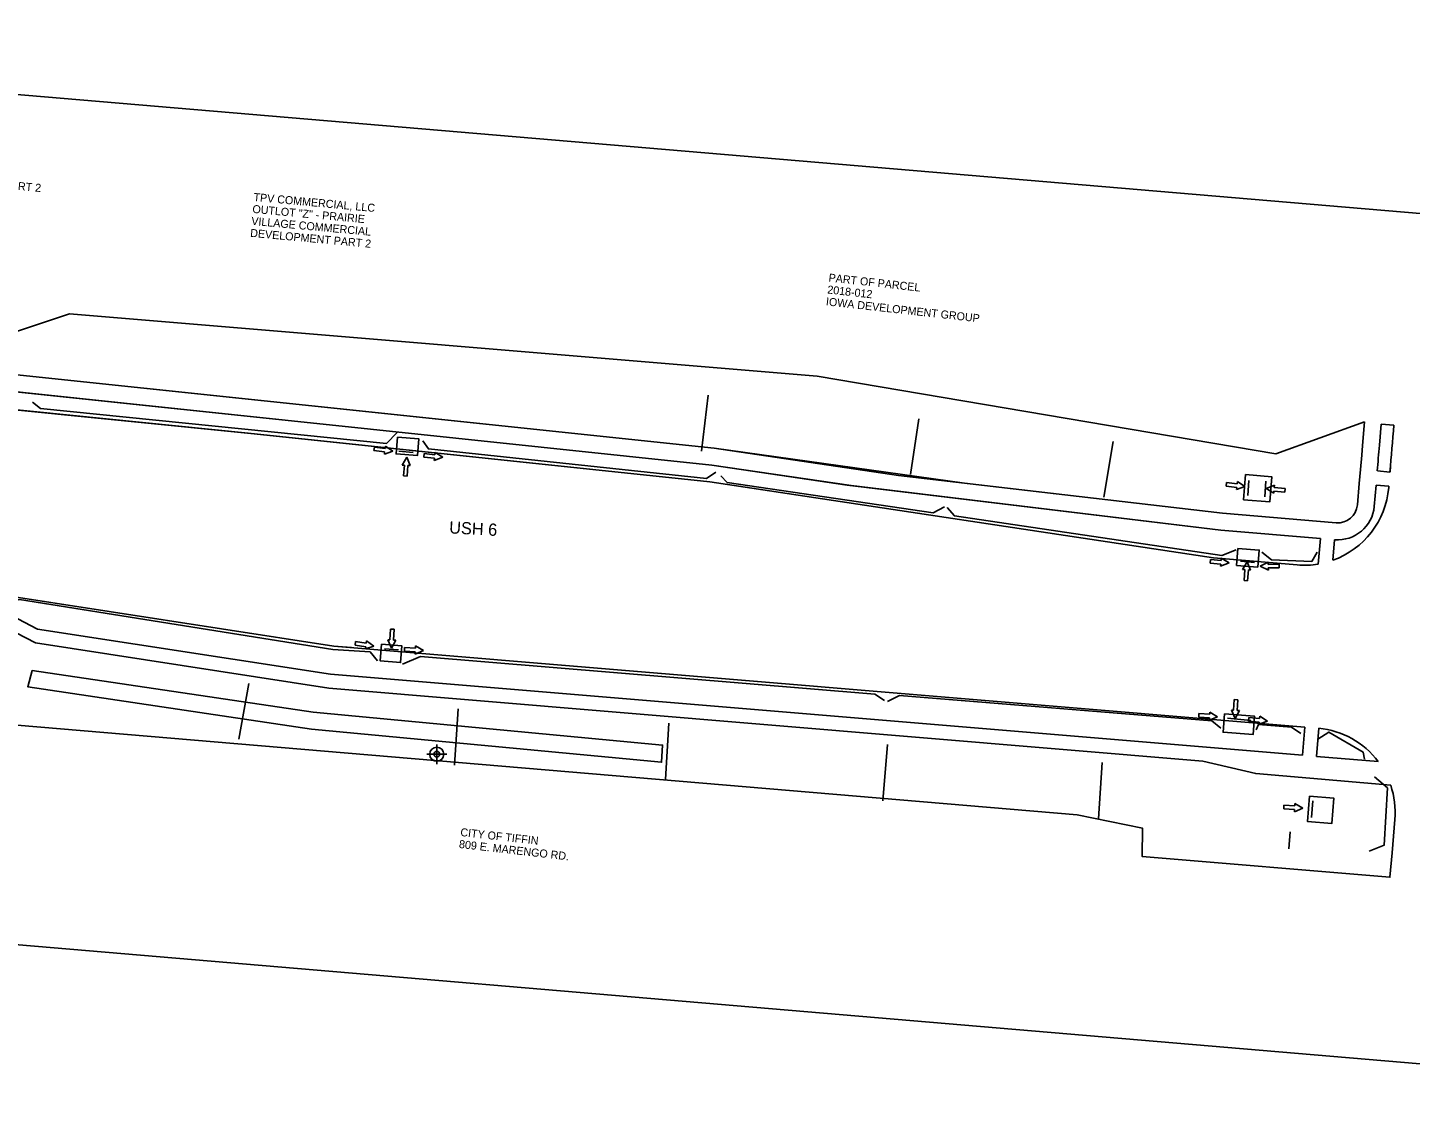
# Model space of a CAD drawing. Extents: x 20499990 to 20505779, y 7953198 to 7954399.
# Drawn here: x 20502718.2 to 20503207.9, y 7953607.1 to 7953985.5 of the extents above; entities that cross this region are included whole.
import ezdxf

# ---------------------------------------------------------------- set-up
doc = ezdxf.new("R2010")
doc.units = 0
for name, color, linetype in [('Building', 7, 'Continuous'), ('ClearGrub', 7, 'Continuous'), ('Curb', 7, 'Continuous'), ('dsnCellElements', 7, 'Continuous'), ('ErosionControl', 7, 'Continuous'), ('NamedBoundary', 7, 'Continuous'), ('Seeding', 7, 'Continuous'), ('Sidewalk', 7, 'Continuous'), ('Text', 7, 'Continuous')]:
    doc.layers.add(name, color=color, linetype=linetype)

msp = doc.modelspace()

# ---------------------------------------------------------------- linework, layer by layer
at = {"layer": 'Building'}
for p, q in [((20503190.96, 7953837.52), (20503191.67, 7953845.98)), ((20503196.96, 7953837.66), (20503197.62, 7953845.17)), ((20503197.63, 7953845.19), (20503202.11, 7953844.82)), ((20503190.68, 7953834.16), (20503190.96, 7953837.52)), ((20503190.26, 7953829.05), (20503190.68, 7953834.16)), ((20503189.82, 7953824.07), (20503190.26, 7953829.05)), ((20503200.7, 7953828.17), (20503196.22, 7953828.55)), ((20503138.13, 7953797.77), (20502959.75, 7953824.69)), ((20503189.15, 7953816.56), (20503189.82, 7953824.07)), ((20503195.13, 7953816.03), (20503195.79, 7953823.54)), ((20503195.8, 7953823.57), (20503200.28, 7953823.19)), ((20503176.04, 7953804.65), (20503175.29, 7953795.59)), ((20503180.43, 7953796.93), (20503181.04, 7953804.23)), ((20503167.85, 7953795.29), (20503138.13, 7953797.77)), ((20502826.66, 7953766.57), (20502648.32, 7953794.05)), ((20502824.89, 7953751.67), (20502720.94, 7953767.64)), ((20503170.48, 7953737.88), (20502826.66, 7953766.57)), ((20502825.48, 7953756.63), (20503169.65, 7953727.91)), ((20503169.65, 7953727.91), (20503170.48, 7953737.88)), ((20503175.47, 7953737.46), (20503174.64, 7953727.5)), ((20503174.64, 7953727.5), (20503196.49, 7953725.67)), ((20503201.45, 7953693.28), (20503202.44, 7953705.11))]:
    msp.add_line(p, q, dxfattribs=at)
for points in [[(20503191.67, 7953845.98), (20503160.23, 7953834.67), (20502997.8, 7953862.16), (20502732.96, 7953884.23), (20502696.7, 7953872.21), (20502598.22, 7953880.54), (20502597.36, 7953880.88)], [(20502596.77, 7953874.12), (20502646.43, 7953869.48), (20502697.39, 7953864.38), (20502801.98, 7953853.37), (20502961.27, 7953836.6), (20503050, 7953824.21), (20503141.39, 7953813.56), (20503181.6, 7953810.21)], [(20502600.82, 7953862.58), (20502601.24, 7953867.37), (20502650.63, 7953863.01), (20502697.4, 7953858.35), (20502809.34, 7953846.56), (20502960.51, 7953830.65), (20503008.42, 7953823.59), (20503140.79, 7953807.58), (20503176.04, 7953804.65)], [(20502959.75, 7953824.69), (20502796.27, 7953841.89), (20502607.78, 7953860.95)], [(20502720.94, 7953767.64), (20502706.88, 7953774.87), (20502647.4, 7953784.09), (20502613.61, 7953787.03), (20502598.23, 7953783.35), (20502571.26, 7953785.7)], [(20502648, 7953789.06), (20502707.64, 7953779.82), (20502721.7, 7953772.58), (20502825.48, 7953756.63)], [(20502567.99, 7953764), (20502613.1, 7953758.85), (20502612.25, 7953748.82), (20502698.25, 7953741.67), (20502701.89, 7953740.37), (20502705.93, 7953739.22), (20503089.85, 7953706.77), (20503113.09, 7953702.02), (20503112.96, 7953691.99), (20503200.66, 7953684.68), (20503201.45, 7953693.28)], [(20503200.94, 7953717.27), (20503153.17, 7953721.39), (20503134.36, 7953725.84), (20502824.89, 7953751.67)]]:
    msp.add_lwpolyline(points, dxfattribs=at)
for centre, radius, start, end in [((20522727.64, 7952187.52), 19595.74, 175.148457, 175.197296), ((20503853.76, 7953779.5), 659.38, 174.93948, 175.73374), ((20503170.34, 7953825.18), 30, 289.6452, 355.1856), ((20503182.18, 7953817.18), 7, 265.2365, 354.9395), ((20503182.18, 7953817.18), 13, 265.2365, 354.9395), ((20503170.34, 7953825.18), 30, 265.2301, 279.4946), ((20503172.54, 7953707.6), 30, 37.0399, 84.393), ((20503172.54, 7953707.6), 30, 355.2385, 18.8077)]:
    msp.add_arc(centre, radius, start, end, dxfattribs=at)
at = {"layer": 'ClearGrub'}
for p, q in [((20502859.58, 7953728.24), (20502866.58, 7953728.24)), ((20502863.08, 7953731.74), (20502863.08, 7953724.74))]:
    msp.add_line(p, q, dxfattribs=at)
for radius in [2.5, 1]:
    msp.add_circle((20502863.08, 7953728.24), radius, dxfattribs=at)
at = {"layer": 'Curb'}
msp.add_line((20503200.24, 7953822.66), (20503200.28, 7953823.19), dxfattribs=at)
at = {"layer": 'dsnCellElements'}
for p, q in [((20502840.82, 7953835.75), (20502840.98, 7953837.01)), ((20502844.61, 7953835.28), (20502840.82, 7953835.75)), ((20502840.98, 7953837.01), (20502844.76, 7953836.54)), ((20502844.76, 7953836.54), (20502844.86, 7953837.33)), ((20502844.86, 7953837.33), (20502847.52, 7953835.55)), ((20502847.52, 7953835.55), (20502844.51, 7953834.49)), ((20502844.51, 7953834.49), (20502844.61, 7953835.28)), ((20502850.8, 7953830.66), (20502852.44, 7953833.41)), ((20502852.44, 7953833.41), (20502853.65, 7953830.45)), ((20502858.47, 7953833.44), (20502858.59, 7953834.71)), ((20502862.27, 7953833.07), (20502858.47, 7953833.44)), ((20502858.59, 7953834.71), (20502862.39, 7953834.33)), ((20502865.18, 7953833.42), (20502862.19, 7953832.27)), ((20502862.19, 7953832.27), (20502862.27, 7953833.07)), ((20502862.39, 7953834.33), (20502862.47, 7953835.12)), ((20502862.47, 7953835.12), (20502865.18, 7953833.42)), ((20502851.59, 7953830.6), (20502850.8, 7953830.66)), ((20502851.31, 7953826.8), (20502851.59, 7953830.6)), ((20502852.57, 7953826.7), (20502851.31, 7953826.8)), ((20502852.86, 7953830.51), (20502852.57, 7953826.7)), ((20502853.65, 7953830.45), (20502852.86, 7953830.51)), ((20503142.64, 7953823.19), (20503142.79, 7953824.45)), ((20503146.42, 7953822.73), (20503142.64, 7953823.19)), ((20503142.79, 7953824.45), (20503146.58, 7953824)), ((20503149.34, 7953823.02), (20503146.33, 7953821.94)), ((20503146.33, 7953821.94), (20503146.42, 7953822.73)), ((20503146.58, 7953824), (20503146.67, 7953824.79)), ((20503146.67, 7953824.79), (20503149.34, 7953823.02)), ((20503156.8, 7953822.33), (20503159.79, 7953823.49)), ((20503159.52, 7953820.64), (20503156.8, 7953822.33)), ((20503159.6, 7953821.43), (20503159.52, 7953820.64)), ((20503163.4, 7953821.08), (20503159.6, 7953821.43)), ((20503159.79, 7953823.49), (20503159.71, 7953822.7)), ((20503159.71, 7953822.7), (20503163.51, 7953822.35)), ((20503163.51, 7953822.35), (20503163.4, 7953821.08)), ((20503136.97, 7953795.91), (20503137.08, 7953797.18)), ((20503137.08, 7953797.18), (20503140.88, 7953796.85)), ((20503140.88, 7953796.85), (20503140.95, 7953797.64)), ((20503140.95, 7953797.64), (20503143.68, 7953795.97)), ((20503140.77, 7953795.58), (20503136.97, 7953795.91)), ((20503143.68, 7953795.97), (20503140.7, 7953794.79)), ((20503140.7, 7953794.79), (20503140.77, 7953795.58)), ((20503148.49, 7953793.67), (20503150.13, 7953796.42)), ((20503149.28, 7953793.61), (20503148.49, 7953793.67)), ((20503149, 7953789.81), (20503149.28, 7953793.61)), ((20503150.13, 7953796.42), (20503151.34, 7953793.46)), ((20503150.55, 7953793.52), (20503150.26, 7953789.71)), ((20503151.34, 7953793.46), (20503150.55, 7953793.52)), ((20503154.73, 7953794.82), (20503157.58, 7953796.29)), ((20503157.61, 7953793.42), (20503154.73, 7953794.82)), ((20503157.58, 7953796.29), (20503157.59, 7953795.49)), ((20503157.59, 7953795.49), (20503161.4, 7953795.53)), ((20503161.42, 7953794.26), (20503157.6, 7953794.22)), ((20503157.6, 7953794.22), (20503157.61, 7953793.42)), ((20503161.4, 7953795.53), (20503161.42, 7953794.26)), ((20503150.26, 7953789.71), (20503149, 7953789.81)), ((20502846.5, 7953768.72), (20502846.66, 7953772.53)), ((20502846.66, 7953772.53), (20502847.93, 7953772.48)), ((20502847.93, 7953772.48), (20502847.77, 7953768.66)), ((20502834.13, 7953766.91), (20502834.32, 7953768.17)), ((20502834.32, 7953768.17), (20502838.1, 7953767.59)), ((20502838.1, 7953767.59), (20502838.21, 7953768.38)), ((20502838.21, 7953768.38), (20502840.83, 7953766.54)), ((20502847.01, 7953765.83), (20502845.7, 7953768.75)), ((20502845.7, 7953768.75), (20502846.5, 7953768.72)), ((20502848.56, 7953768.63), (20502847.01, 7953765.83)), ((20502847.77, 7953768.66), (20502848.56, 7953768.63)), ((20502837.9, 7953766.34), (20502834.13, 7953766.91)), ((20502840.83, 7953766.54), (20502837.79, 7953765.55)), ((20502837.79, 7953765.55), (20502837.9, 7953766.34)), ((20502851.6, 7953764.74), (20502851.67, 7953766.01)), ((20502855.41, 7953764.53), (20502851.6, 7953764.74)), ((20502851.67, 7953766.01), (20502855.48, 7953765.8)), ((20502858.31, 7953765.01), (20502855.37, 7953763.74)), ((20502855.37, 7953763.74), (20502855.41, 7953764.53)), ((20502855.48, 7953765.8), (20502855.53, 7953766.6)), ((20502855.53, 7953766.6), (20502858.31, 7953765.01)), ((20503145.3, 7953743.8), (20503145.48, 7953747.61)), ((20503145.48, 7953747.61), (20503146.75, 7953747.55)), ((20503146.75, 7953747.55), (20503146.57, 7953743.74)), ((20503132.95, 7953741.38), (20503133.04, 7953742.65)), ((20503133.04, 7953742.65), (20503136.84, 7953742.38)), ((20503136.84, 7953742.38), (20503136.9, 7953743.17)), ((20503136.9, 7953743.17), (20503139.65, 7953741.54)), ((20503145.8, 7953740.91), (20503144.51, 7953743.84)), ((20503144.51, 7953743.84), (20503145.3, 7953743.8)), ((20503147.37, 7953743.7), (20503145.8, 7953740.91)), ((20503146.57, 7953743.74), (20503147.37, 7953743.7)), ((20503136.75, 7953741.11), (20503132.95, 7953741.38)), ((20503139.65, 7953741.54), (20503136.7, 7953740.32)), ((20503136.7, 7953740.32), (20503136.75, 7953741.11)), ((20503150.55, 7953739.96), (20503150.67, 7953741.23)), ((20503154.36, 7953739.63), (20503150.55, 7953739.96)), ((20503150.67, 7953741.23), (20503154.47, 7953740.9)), ((20503157.26, 7953740.01), (20503154.29, 7953738.84)), ((20503154.29, 7953738.84), (20503154.36, 7953739.63)), ((20503154.47, 7953740.9), (20503154.54, 7953741.69)), ((20503154.54, 7953741.69), (20503157.26, 7953740.01)), ((20503163.07, 7953708.96), (20503163.15, 7953710.23)), ((20503166.87, 7953708.69), (20503163.07, 7953708.96)), ((20503163.15, 7953710.23), (20503166.96, 7953709.96)), ((20503169.77, 7953709.12), (20503166.82, 7953707.9)), ((20503166.82, 7953707.9), (20503166.87, 7953708.69)), ((20503166.96, 7953709.96), (20503167.02, 7953710.75)), ((20503167.02, 7953710.75), (20503169.77, 7953709.12))]:
    msp.add_line(p, q, dxfattribs=at)
at = {"layer": 'ErosionControl'}
for p, q in [((20502956.81, 7953835.52), (20502959.21, 7953855.37)), ((20503030.92, 7953827.27), (20503033.83, 7953847.06)), ((20503099.37, 7953819.23), (20503102.66, 7953838.96)), ((20502854.66, 7953835.13), (20502849.68, 7953835.55)), ((20503150.35, 7953819.84), (20503150.69, 7953825.23)), ((20503156.67, 7953824.93), (20503156.37, 7953819.37)), ((20503195.13, 7953816.03), (20503195.79, 7953823.54)), ((20503195.8, 7953823.57), (20503200.28, 7953823.19)), ((20503200.24, 7953822.66), (20503200.28, 7953823.19)), ((20503180.43, 7953796.93), (20503181.04, 7953804.23)), ((20503181.1, 7953804.23), (20503181.04, 7953804.23)), ((20503152.7, 7953796.2), (20503147.72, 7953796.61)), ((20502832.81, 7953766.06), (20502826.66, 7953766.57)), ((20502844.53, 7953765.59), (20502849.51, 7953765.19)), ((20502792.93, 7953733.63), (20502796.48, 7953753.31)), ((20502869.34, 7953724.33), (20502870.69, 7953744.28)), ((20502944.04, 7953719.25), (20502945.25, 7953739.22)), ((20503143.1, 7953740.97), (20503151.4, 7953740.21)), ((20503021.07, 7953711.78), (20503022.69, 7953731.71)), ((20503097.44, 7953705.34), (20503098.71, 7953725.3)), ((20503172.92, 7953705.88), (20503173.39, 7953711.8)), ((20503165.33, 7953700.72), (20503164.83, 7953694.74))]:
    msp.add_line(p, q, dxfattribs=at)
for points in [[(20502719.82, 7953852.96), (20502722.68, 7953850.68), (20502845.28, 7953838.31), (20502849.01, 7953842.14)], [(20502858.1, 7953839.2), (20502860.12, 7953836.36), (20502958.63, 7953825.9), (20502961.86, 7953828.13)], [(20502963.72, 7953826.85), (20502965.9, 7953824.45), (20503038.84, 7953813.79), (20503042.96, 7953815.86)], [(20503043.88, 7953815.63), (20503046.4, 7953812.65), (20503141.1, 7953798.67), (20503146.25, 7953800.62)], [(20503155.28, 7953799.85), (20503158.69, 7953797.04), (20503172.99, 7953796.51), (20503174.93, 7953799.79)], [(20502842.12, 7953761.3), (20502839.46, 7953764.5), (20502826.3, 7953765.33), (20502715.26, 7953783.03), (20502709.93, 7953781.73)], [(20503021.62, 7953747.27), (20503018.2, 7953749.55), (20502857.26, 7953762.87), (20502850.96, 7953760.14)], [(20503140.77, 7953737.51), (20503137.58, 7953740.1), (20503026.95, 7953749.08), (20503022.67, 7953746.98)], [(20503153.25, 7953736.85), (20503154.1, 7953738.79), (20503165.77, 7953737.83), (20503169.13, 7953735.59)], [(20503175.17, 7953733.61), (20503179.05, 7953736.12), (20503191.15, 7953729.04), (20503191.68, 7953726.46)], [(20503195.18, 7953720.21), (20503199.82, 7953716.33), (20503198.68, 7953696.09), (20503193.36, 7953693.88)]]:
    msp.add_lwpolyline(points, dxfattribs=at)
for points in [[(20502849.14, 7953840.58), (20502848.67, 7953834.6), (20502856.21, 7953834), (20502856.69, 7953839.98)], [(20503149.53, 7953827.28), (20503148.82, 7953818.35), (20503158.08, 7953817.62), (20503158.79, 7953826.54)], [(20503146.81, 7953801.12), (20503146.34, 7953795.14), (20503153.88, 7953794.54), (20503154.36, 7953800.52)], [(20502843.51, 7953767.17), (20502850.74, 7953766.6), (20502850.27, 7953760.7), (20502843.05, 7953761.28)], [(20502719.78, 7953757.92), (20502819.27, 7953743.09), (20502943.06, 7953731.51), (20502942.67, 7953725.39), (20502818.67, 7953737.12), (20502718.22, 7953752.12)], [(20503142.11, 7953742.52), (20503152.72, 7953741.68), (20503152.2, 7953735.19), (20503141.59, 7953736.03)], [(20503172.21, 7953713.4), (20503180.77, 7953712.73), (20503180.05, 7953703.7), (20503171.5, 7953704.38)]]:
    msp.add_lwpolyline(points, close=True, dxfattribs=at)
for centre, radius, start, end in [((20503170.34, 7953825.18), 30, 289.6452, 355.1856), ((20503182.18, 7953817.18), 13, 265.2365, 354.9395)]:
    msp.add_arc(centre, radius, start, end, dxfattribs=at)
at = {"layer": 'NamedBoundary'}
msp.add_lwpolyline([(20502435.82, 7953985.54), (20502410.46, 7953686.62), (20503347.59, 7953607.1), (20503372.96, 7953906.03)], close=True, dxfattribs=at)
at = {"layer": 'Seeding'}
for p, q in [((20503190.96, 7953837.52), (20503191.67, 7953845.98)), ((20503196.96, 7953837.66), (20503197.62, 7953845.17)), ((20503197.63, 7953845.19), (20503202.11, 7953844.82)), ((20503190.68, 7953834.16), (20503190.96, 7953837.52)), ((20503190.26, 7953829.05), (20503190.68, 7953834.16)), ((20503189.82, 7953824.07), (20503190.26, 7953829.05)), ((20503200.7, 7953828.17), (20503196.22, 7953828.55)), ((20503138.13, 7953797.77), (20502959.75, 7953824.69)), ((20503189.15, 7953816.56), (20503189.82, 7953824.07)), ((20503195.13, 7953816.03), (20503195.79, 7953823.54)), ((20503195.8, 7953823.57), (20503200.28, 7953823.19)), ((20503176.04, 7953804.65), (20503175.29, 7953795.59)), ((20503180.43, 7953796.93), (20503181.04, 7953804.23)), ((20503167.85, 7953795.29), (20503138.13, 7953797.77)), ((20502826.66, 7953766.57), (20502648.32, 7953794.05)), ((20502824.89, 7953751.67), (20502720.94, 7953767.64)), ((20502832.81, 7953766.06), (20502826.66, 7953766.57)), ((20503170.48, 7953737.88), (20502826.66, 7953766.57)), ((20502825.48, 7953756.63), (20503169.65, 7953727.91)), ((20503169.65, 7953727.91), (20503170.48, 7953737.88)), ((20503175.47, 7953737.46), (20503174.64, 7953727.5)), ((20503174.64, 7953727.5), (20503196.49, 7953725.67)), ((20503201.45, 7953693.28), (20503202.44, 7953705.11))]:
    msp.add_line(p, q, dxfattribs=at)
for points in [[(20503191.67, 7953845.98), (20503160.23, 7953834.67), (20502997.8, 7953862.16), (20502732.96, 7953884.23), (20502696.7, 7953872.21), (20502598.22, 7953880.54), (20502597.36, 7953880.88)], [(20502596.77, 7953874.12), (20502650.75, 7953869.08), (20502697.39, 7953864.38), (20502818.79, 7953851.6), (20502961.27, 7953836.6), (20503026.56, 7953826.95), (20503141.39, 7953813.56), (20503181.6, 7953810.21)], [(20502600.82, 7953862.58), (20502601.24, 7953867.37), (20502646.05, 7953863.46), (20502695.83, 7953858.51), (20502809.34, 7953846.56), (20502960.51, 7953830.65), (20503009.88, 7953823.38), (20503140.79, 7953807.58), (20503176.04, 7953804.65)], [(20502959.75, 7953824.69), (20502798.39, 7953841.68), (20502612.16, 7953860.35)], [(20502720.94, 7953767.64), (20502706.88, 7953774.87), (20502647.4, 7953784.09), (20502613.61, 7953787.03), (20502598.23, 7953783.35), (20502571.26, 7953785.7)], [(20502648, 7953789.06), (20502707.64, 7953779.82), (20502721.7, 7953772.58), (20502825.48, 7953756.63)], [(20502567.99, 7953764), (20502613.1, 7953758.85), (20502612.25, 7953748.82), (20502698.25, 7953741.67), (20502701.89, 7953740.37), (20502705.93, 7953739.22), (20503089.85, 7953706.77), (20503113.09, 7953702.02), (20503112.96, 7953691.99), (20503200.66, 7953684.68), (20503201.45, 7953693.28)], [(20503200.94, 7953717.27), (20503153.17, 7953721.39), (20503134.36, 7953725.84), (20502824.89, 7953751.67)]]:
    msp.add_lwpolyline(points, dxfattribs=at)
for centre, radius, start, end in [((20522727.65, 7952187.52), 19595.76, 175.148457, 175.197296), ((20503853.76, 7953779.5), 659.38, 174.93948, 175.73374), ((20503170.34, 7953825.18), 30, 289.6452, 355.1856), ((20503182.18, 7953817.18), 7, 265.2365, 354.9395), ((20503182.18, 7953817.18), 13, 265.2365, 354.9395), ((20503170.34, 7953825.18), 30, 265.2301, 279.4946), ((20503172.54, 7953707.6), 30, 37.0399, 84.393), ((20503172.54, 7953707.6), 30, 355.2385, 18.8077)]:
    msp.add_arc(centre, radius, start, end, dxfattribs=at)
at = {"layer": 'Sidewalk'}
msp.add_line((20503181.1, 7953804.23), (20503181.04, 7953804.23), dxfattribs=at)

# ---------------------------------------------------------------- texts
at = {"layer": 'Text'}
for s, height, rotation, p in [('COMMERCIAL DEVELOPMENT PART 2', 2.8346, 354.7645, (20502653.37, 7953933.7)), ('TPV COMMERCIAL, LLC', 2.8346, 354.7645, (20502798.06, 7953924.2)), ('OUTLOT "Z" - PRAIRIE ', 2.8346, 354.7645, (20502797.67, 7953919.97)), ('DEVELOPMENT PART 2', 2.8346, 354.7645, (20502796.89, 7953911.5)), ('VILLAGE COMMERCIAL ', 2.8346, 354.7645, (20502797.28, 7953915.74)), ('PART OF PARCEL', 2.8346, 353.6591, (20503001.74, 7953895.68)), ('IOWA DEVELOPMENT GROUP', 2.8346, 353.6591, (20503000.8, 7953887.23)), ('2018-012', 2.835, 353.6591, (20503001.27, 7953891.45)), ('USH 6', 4.32, 356.9, (20502867.38, 7953806.46)), ('CITY OF TIFFIN', 2.8346, 353.4901, (20502871.31, 7953699.32)), ('809 E. MARENGO RD.', 2.8346, 353.4901, (20502870.82, 7953695.09))]:
    msp.add_text(s, height=height, rotation=rotation, dxfattribs=at).set_placement(p)

doc.saveas('drawing.dxf')
